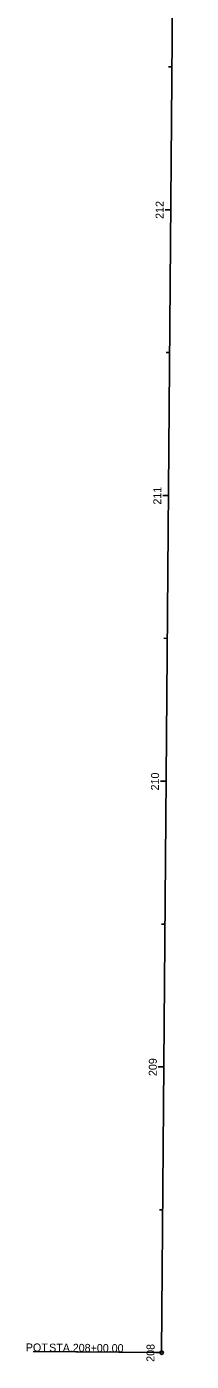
# Model space of a CAD drawing. Extents: x 1504466 to 1504712, y 322450 to 329957.
# Drawn here: x 1504504.8 to 1504562.5, y 322449.6 to 322916.7 of the extents above; entities that cross this region are included whole.
import ezdxf

# ---------------------------------------------------------------- set-up
doc = ezdxf.new("R2010")
doc.units = 0
for name, color, linetype in [('GE_X_Alignment', 7, 'Continuous'), ('GE_X_Alignment_100_Cardinal_Points', 7, 'Continuous'), ('GE_X_Alignment_100_Stations', 7, 'Continuous'), ('GE_X_Alignment_500_Cardinal_Points', 7, 'Continuous'), ('GE_X_Alignment_500_Stations', 7, 'Continuous')]:
    doc.layers.add(name, color=color, linetype=linetype)

msp = doc.modelspace()

# ---------------------------------------------------------------- linework, layer by layer
at = {"layer": 'GE_X_Alignment'}
msp.add_line((1504552.13, 322452.59), (1504562.54, 323755.45), dxfattribs=at)
at = {"layer": 'GE_X_Alignment_100_Cardinal_Points'}
msp.add_line((1504552.13, 322452.59), (1504507.13, 322452.95), dxfattribs=at)
msp.add_circle((1504552.13, 322452.59), 0.6, dxfattribs=at)
at = {"layer": 'GE_X_Alignment_100_Stations'}
for p, q in [((1504555.73, 322902.58), (1504554.53, 322902.59)), ((1504555.33, 322852.58), (1504553.33, 322852.59)), ((1504554.93, 322802.58), (1504553.73, 322802.59)), ((1504554.53, 322752.58), (1504552.53, 322752.6)), ((1504554.13, 322702.58), (1504552.93, 322702.59)), ((1504553.73, 322652.59), (1504551.73, 322652.6)), ((1504553.33, 322602.59), (1504552.13, 322602.6)), ((1504552.93, 322552.59), (1504550.93, 322552.6)), ((1504552.53, 322502.59), (1504551.33, 322502.6)), ((1504552.13, 322452.59), (1504550.13, 322452.61))]:
    msp.add_line(p, q, dxfattribs=at)
at = {"layer": 'GE_X_Alignment_500_Cardinal_Points'}
msp.add_line((1504552.13, 322452.59), (1504507.13, 322452.95), dxfattribs=at)
msp.add_circle((1504552.13, 322452.59), 0.6, dxfattribs=at)
at = {"layer": 'GE_X_Alignment_500_Stations'}
for p, q in [((1504555.33, 322852.58), (1504554.13, 322852.59)), ((1504554.53, 322752.58), (1504553.33, 322752.59)), ((1504553.73, 322652.59), (1504551.73, 322652.6)), ((1504552.93, 322552.59), (1504551.73, 322552.6)), ((1504552.13, 322452.59), (1504550.93, 322452.6))]:
    msp.add_line(p, q, dxfattribs=at)

# ---------------------------------------------------------------- texts
at = {"layer": 'GE_X_Alignment_100_Cardinal_Points'}
for s, p in [('POT', (1504504.53, 322453.01)), (' STA. ', (1504511.66, 322452.95)), ('208+00.00', (1504520.98, 322452.88))]:
    msp.add_text(s, height=2.8, rotation=359.5421, dxfattribs=at).set_placement(p)
at = {"layer": 'GE_X_Alignment_100_Stations'}
for s, p in [('212', (1504552.8, 322849.39)), ('211', (1504552, 322749.38)), ('210', (1504551.2, 322649.34)), ('209', (1504550.4, 322549.38)), ('208', (1504549.6, 322449.36))]:
    msp.add_text(s, height=2.8, rotation=89.5421, dxfattribs=at).set_placement(p)
at = {"layer": 'GE_X_Alignment_500_Cardinal_Points'}
for s, p in [('POT', (1504504.53, 322453.01)), (' STA. ', (1504511.66, 322452.95)), ('208+00.00', (1504520.98, 322452.88))]:
    msp.add_text(s, height=2.8, rotation=359.5421, dxfattribs=at).set_placement(p)
at = {"layer": 'GE_X_Alignment_500_Stations'}
msp.add_text('210', height=2.8, rotation=89.5421, dxfattribs=at).set_placement((1504551.2, 322649.34))

doc.saveas('drawing.dxf')
